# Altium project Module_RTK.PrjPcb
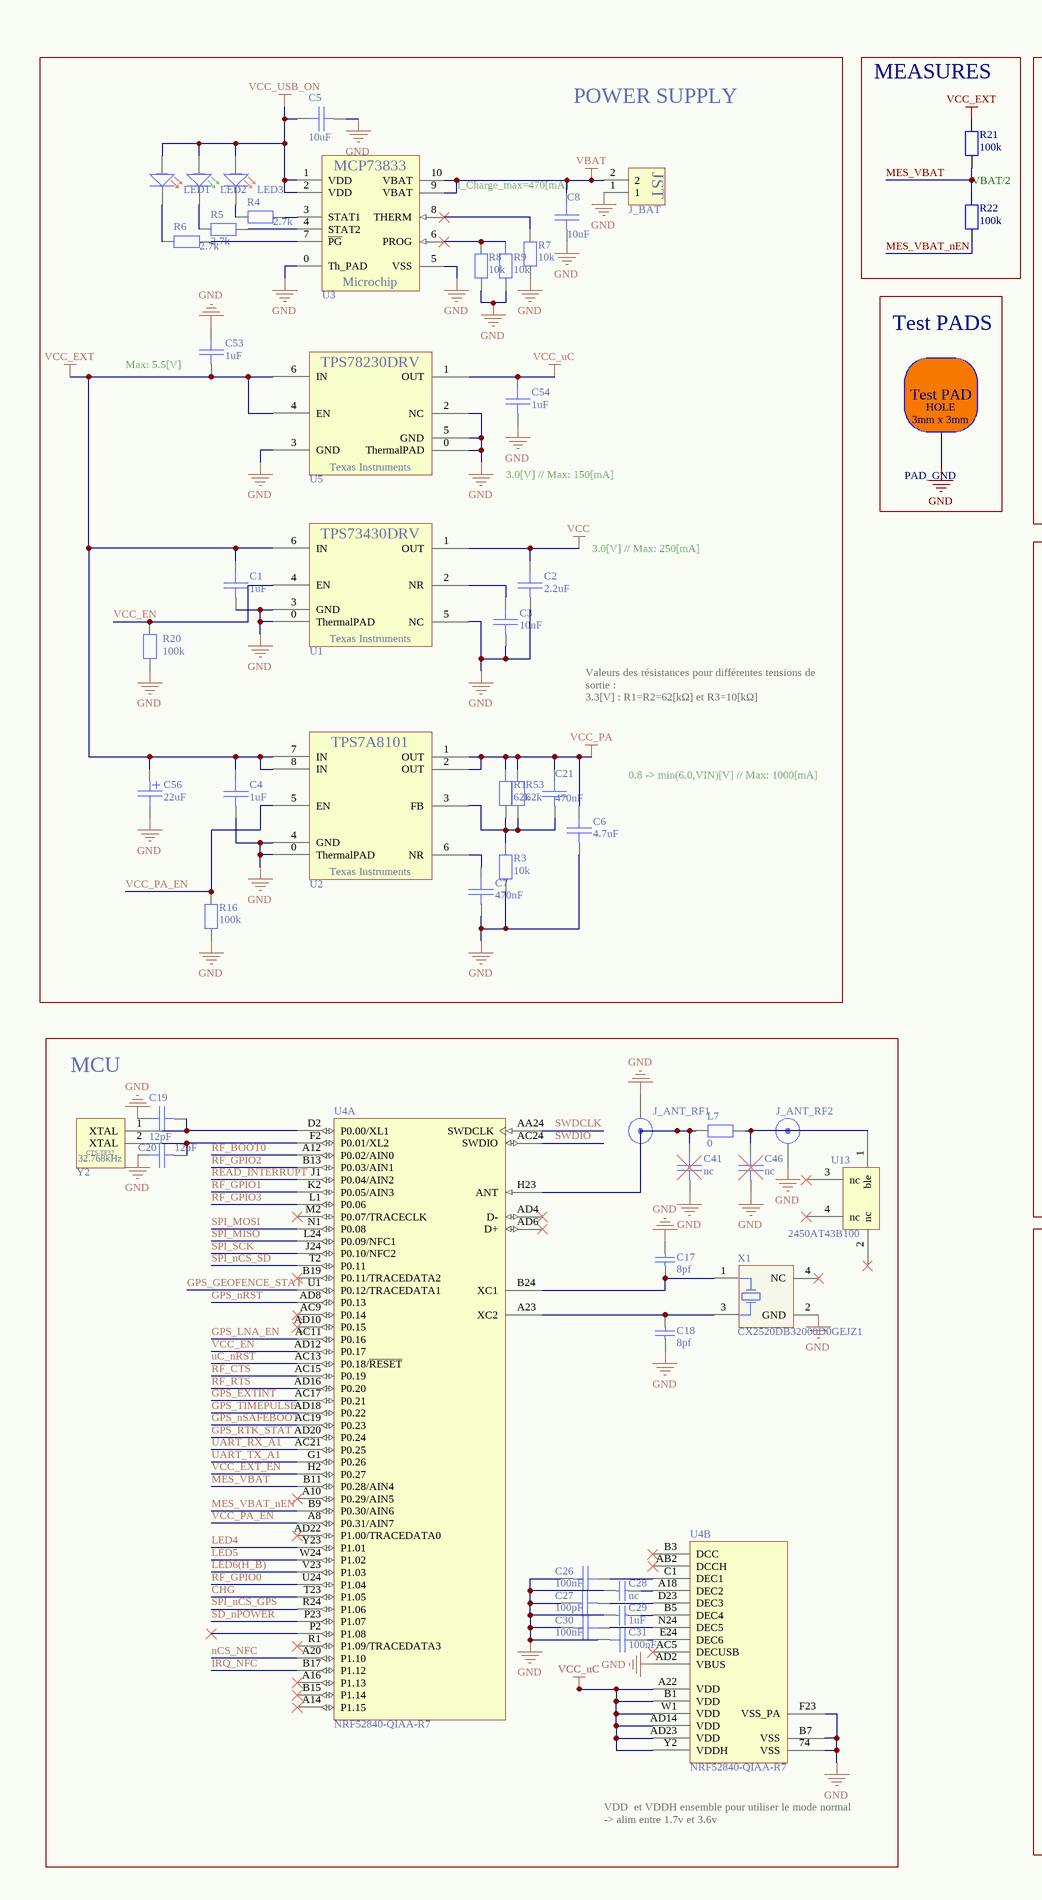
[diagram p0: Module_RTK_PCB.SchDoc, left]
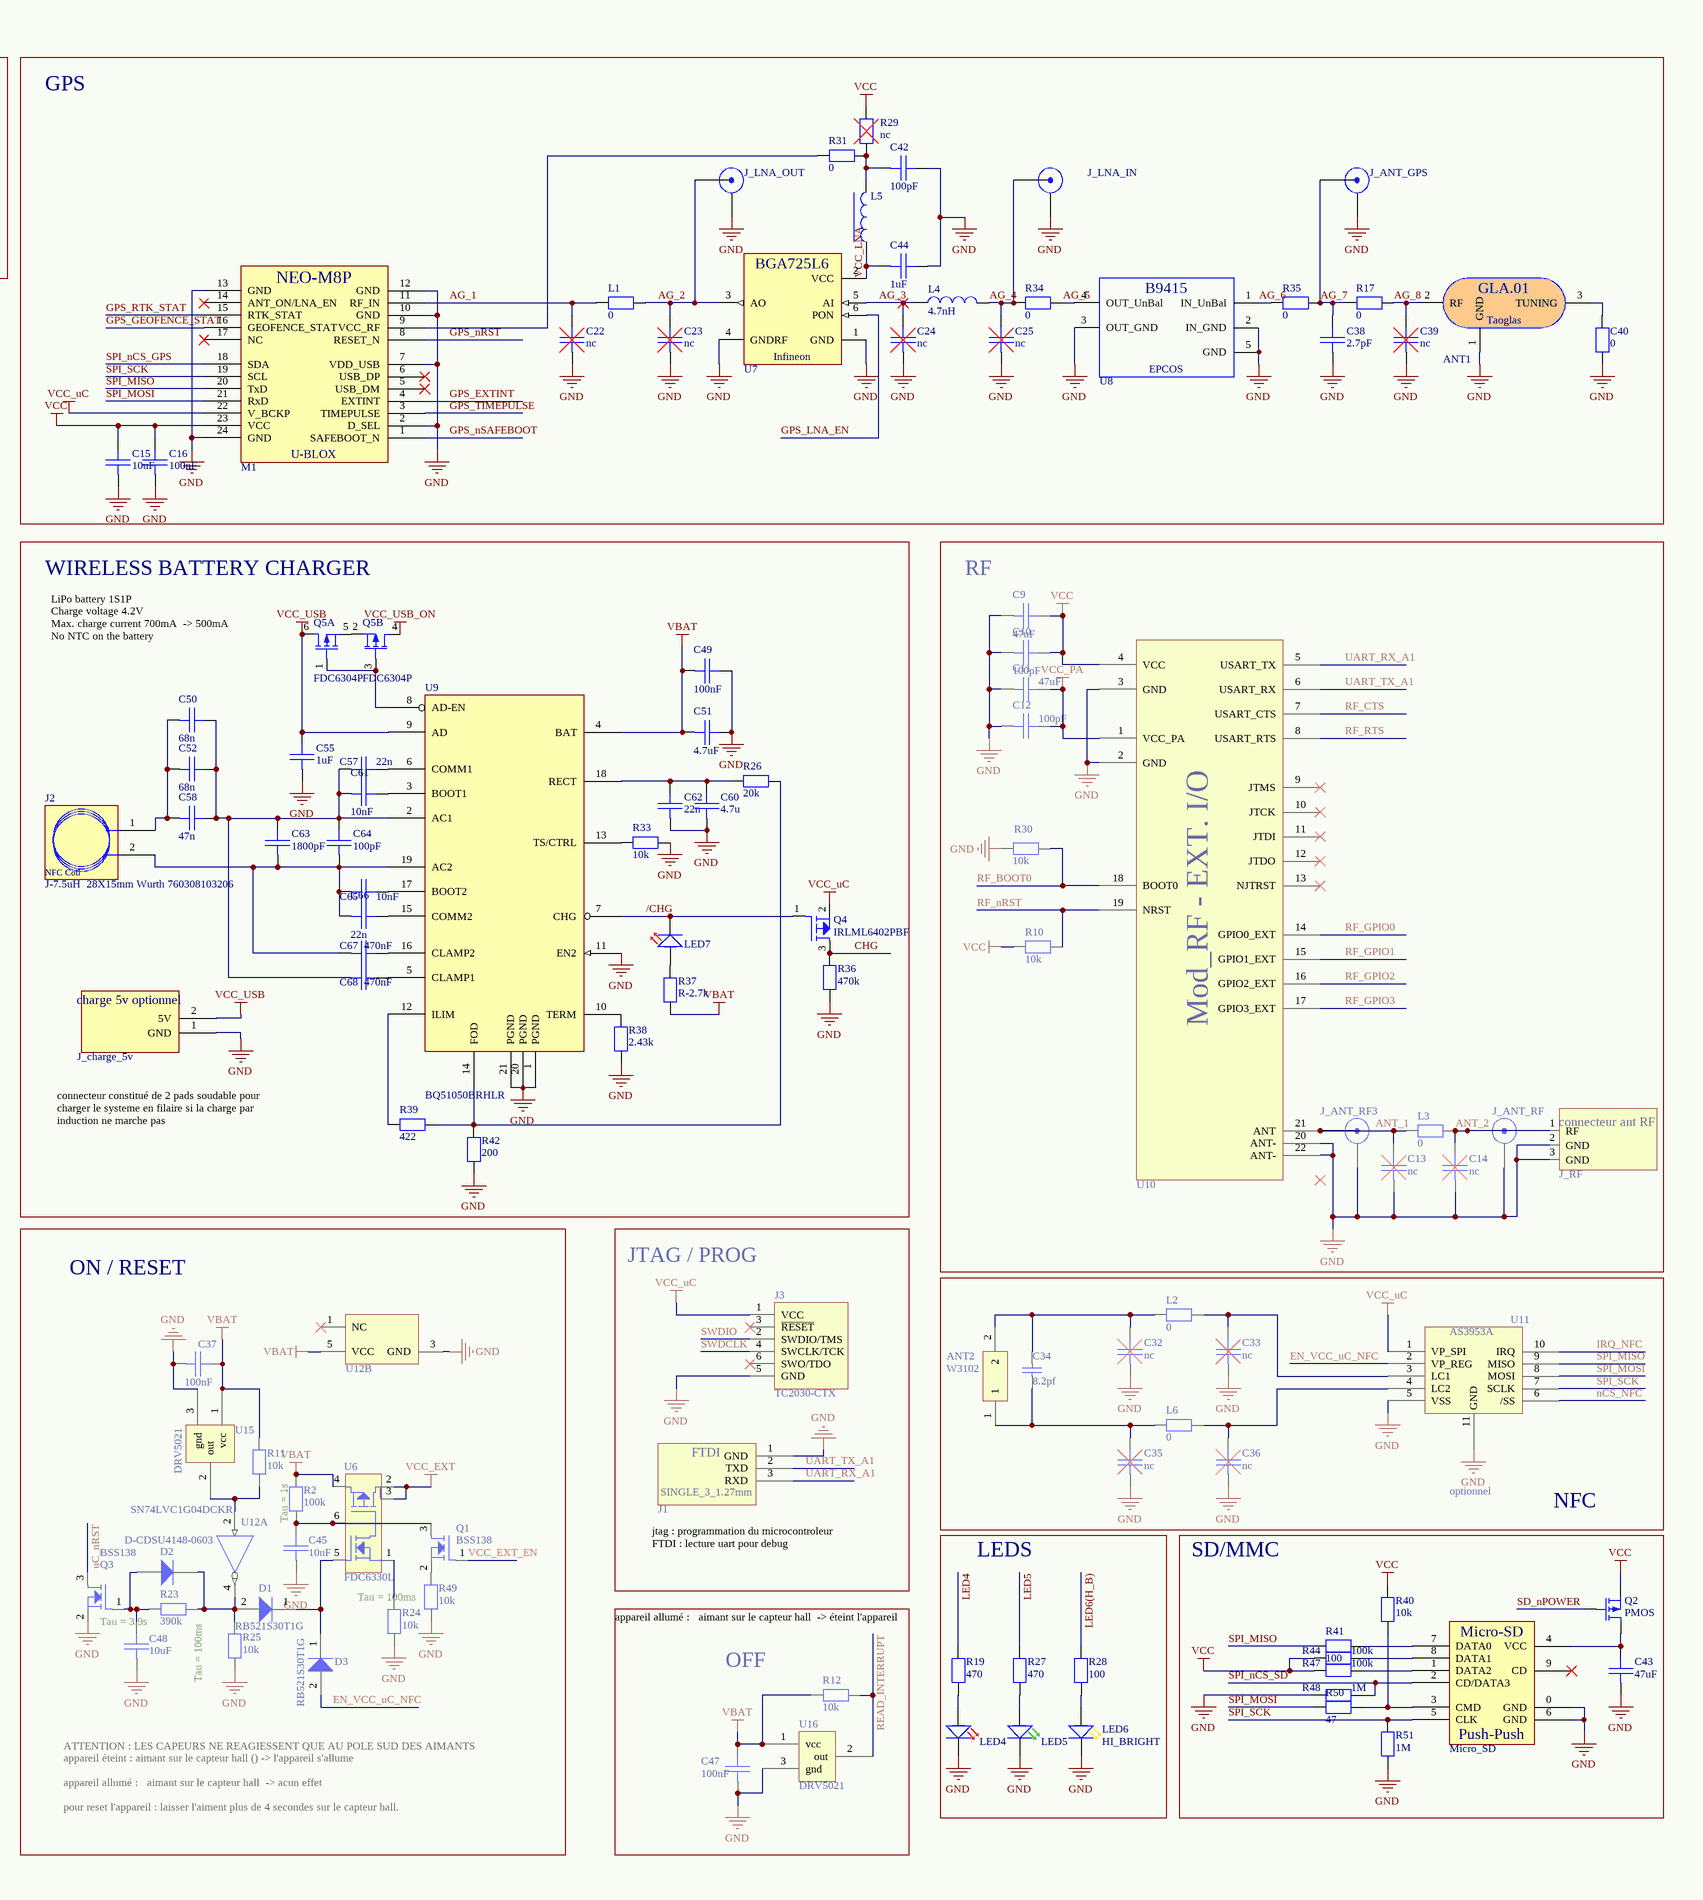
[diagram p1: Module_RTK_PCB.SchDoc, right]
1 sheet, 168 parts. Net scope: global (net labels, ports and power ports of the same name join across sheets).
Board file: Module_RTK_PCB.PcbDoc

## Sheet Module_RTK_PCB.SchDoc: Module_RTK
size A2; DrawnBy: A.B; Organization: MIS Institute; Address1: HEIG-VD; Address2: Rue Galilée 15; Address3: 1400 Yverdon-les-Bains; Address4: Switzerland; PageSetup: Record=PageOptions¦CenterHorizontal=True¦CenterVertical=True¦PrintScale=0.50¦XCorrection=1.00¦YCorrection=1.00¦PrintKind=0¦BorderSize=5000000¦LeftOffset=0¦BottomOffset=0¦Orientation=2¦PaperLength=1000¦PaperWidth=1000¦Scale=100¦PaperSource=7¦PrintQuality=-3¦MediaType=1¦DitherType=10¦PrintScaleMode=1¦PaperKind=A4 (210 x 297 mm)¦PaperIndex=9

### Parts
ANT1  Taoglas-GLA.01  [Taoglas-GLA.01]  (value not drawn)
ANT2  W3102  [W3102]
C1  value 1uF  [SM/C_0805]  (hidden comment: C-1uF-0805)
C2  value 2.2uF  [SM/C_0805]  (hidden comment: C-2.2uF-0805)
C3  value 10nF  [SM/C_0603]  (hidden comment: C-10nF-0603)
C4  value 1uF  [SM/C_0805]  (hidden comment: C-1uF-0805)
C5  value 10uF  [SM/C_0603]  (hidden comment: C-10uF-0603)
C6  value 4.7uF  [SM/C_0805]  (hidden comment: C-4.7uF-0805)
C7  value 470nF  [SM/C_0603]  (hidden comment: C-470nF-0603)
C8  value 10uF  [SM/C_0603]  (hidden comment: C-10uF-0603)
C9  value 47uF  [SM/C_0805]  (hidden comment: C-47uF-0805)
C10  value 100pF  [SM/C_0603]  (hidden comment: C-100pF-0603)
C11  value 47uF  [SM/C_0805]  (hidden comment: C-47uF-0805)
C12  value 100pF  [SM/C_0603]  (hidden comment: C-100pF-0603)
C13  value nc  [SM/C_0402]  (hidden comment: C-nc-0402)
C14  value nc  [SM/C_0402]  (hidden comment: C-nc-0402)
C15  value 10uF  [SM/C_0603]  (hidden comment: C-10uF-0603)
C16  value 100nF  [SM/C_0603]  (hidden comment: C-100nF-0603)
C17  8pf  [CAPC1608X90X35LL15T15]
C18  8pf  [CAPC1608X90X35LL15T15]
C19  value 12pF  [SM/C_0603]  (hidden comment: C-12pF-0603-2%-NP0)
C20  value 12pF  [SM/C_0603]  (hidden comment: C-12pF-0603-2%-NP0)
C21  value 470nF  [SM/C_0603]  (hidden comment: C-470nF-0603)
C22  value nc  [SM/C_0402]  (hidden comment: C-nc-0402)
C23  value nc  [SM/C_0402]  (hidden comment: C-nc-0402)
C24  value nc  [SM/C_0402]  (hidden comment: C-nc-0402)
C25  value nc  [SM/C_0402]  (hidden comment: C-nc-0402)
C26  value 100nF  [SM/C_0603]  (hidden comment: C-100nF-0603)
C27  value 100pF  [SM/C_0402]  (hidden comment: C-100pF 0402 NPO 5%)
C28  nc  [CAPC1709X95X35LL10T25]
C29  1uF  [CAPC1709X95X35LL10T25]
C30  value 100nF  [SM/C_0603]  (hidden comment: C-100nF-0603)
C31  value 100nF  [SM/C_0603]  (hidden comment: C-100nF-0603)
C32  value nc  [SM/C_0402]  (hidden comment: C-nc-0402)
C33  value nc  [SM/C_0402]  (hidden comment: C-nc-0402)
C34  value 8.2pf  [CAPC1508X91X25LL25T13]  (hidden comment: 06032U8R2CAT2A)
C35  value nc  [SM/C_0402]  (hidden comment: C-nc-0402)
C36  value nc  [SM/C_0402]  (hidden comment: C-nc-0402)
C37  value 100nF  [SM/C_0603]  (hidden comment: C-100nF-0603)
C38  value 2.7pF  [SM/C_0402]  (hidden comment: C-2.7pF-0402)
C39  value nc  [SM/C_0402]  (hidden comment: C-nc-0402)
C40  value 0  [SM/R_0402]  (hidden comment: R-0-0402)
C41  value nc  [SM/C_0402]  (hidden comment: C-nc-0402)
C42  value 100pF  [SM/C_0402]  (hidden comment: C-100pF-0402)
C43  value 47uF  [SM/C_0805]  (hidden comment: C-47uF-0805)
C44  value 1uF  [SM/C_0603]  (hidden comment: C-1uF-0603)
C45  value 10uF  [SM/C_0603]  (hidden comment: C-10uF-0603)
C46  value nc  [SM/C_0402]  (hidden comment: C-nc-0402)
C47  value 100nF  [SM/C_0603]  (hidden comment: C-100nF-0603)
C48  value 10uF  [SM/C_0603]  (hidden comment: C-10uF-0603)
C49  value 100nF  [SM/C_0603]  (hidden comment: C-100nF-0603)
C50  value 68n  [SM/C_0402]  (hidden comment: C-68n 0402 X7R)
C51  value 4.7uF  [SM/C_0603]  (hidden comment: C-4.7uF-0603)
C52  value 68n  [SM/C_0402]  (hidden comment: C-68n 0402 X7R)
C53  value 1uF  [SM/C_0603]  (hidden comment: C-1uF-0603)
C54  value 1uF  [SM/C_0603]  (hidden comment: C-1uF-0603)
C55  value 1uF  [SM/C_0805]  (hidden comment: C-1uF-0805)
C56  value 22uF  [SM/C_0805_POL]  (hidden comment: C-22uF-0805-6.3V-TANT)
C57  value 22n  [SM/C_0402]  (hidden comment: C-22n 0402 X7R)
C58  value 47n  [SM/C_0603]  (hidden comment: C-47n 0603 X7R)
C60  value 4.7u  [SM/C_0603]  (hidden comment: C-4.7u 0603 X5R 16V)
C61  value 10nF  [SM/C_0402]  (hidden comment: C-10nF 0402 X7R 5%)
C62  value 22n  [SM/C_0402]  (hidden comment: C-22n 0402 X7R 16V)
C63  value 1800pF  [SM/C_0603]  (hidden comment: C-1800pF 0603 NPO 5%)
C64  value 100pF  [SM/C_0402]  (hidden comment: C-100pF 0402 NPO 5%)
C65  value 10nF  [SM/C_0402]  (hidden comment: C-10nF 0402 X7R 5%)
C66  value 22n  [SM/C_0402]  (hidden comment: C-22n 0402 X7R)
C67  value 470nF  [SM/C_0603]  (hidden comment: C-470nF-0603)
C68  value 470nF  [SM/C_0603]  (hidden comment: C-470nF-0603)
D1  RB521S30T1G  [ONSC-SOD-523-2-502-01_V]
D2  D-CDSU4148-0603  [0603/SOD-523F_Diode]
D3  RB521S30T1G  [ONSC-SOD-523-2-502-01_V]
J1  FTDI  [SINGLE_3_1.27mm]  (value not drawn)
J2  J-7.5uH  28X15mm Wurth 760308103206  [WE-WPCC]
J3  TC2030-CTX  [TC2030-IDC]  (no BOM)
J_ANT_GPS  U.FL-R-SMT  [U.FL-R-SMT]  (value not drawn)
J_ANT_RF  U.FL-R-SMT  [U.FL-R-SMT]  (value not drawn)
J_ANT_RF1  U.FL-R-SMT  [U.FL-R-SMT]  (value not drawn)
J_ANT_RF2  U.FL-R-SMT  [U.FL-R-SMT]  (value not drawn)
J_ANT_RF3  U.FL-R-SMT  [U.FL-R-SMT]  (value not drawn)
J_BAT  S2B-PH-K-S  [S2B-PH-K-S]  (value not drawn)
J_charge_5v  charge 5v optionnel (fil a souder)  [2 pads soudable]  (value not drawn)
J_LNA_IN  U.FL-R-SMT  [U.FL-R-SMT]  (value not drawn)
J_LNA_OUT  U.FL-R-SMT  [U.FL-R-SMT]  (value not drawn)
J_RF  FTDI  [connecteur ant RF]  (value not drawn)
L1  value 0  [SM/R_0402]  (hidden comment: R-0-0402)
L2  value 0  [SM/R_0402]  (hidden comment: R-0-0402)
L3  value 0  [SM/R_0402]  (hidden comment: R-0-0402)
L4  value 4.7nH  [SM/L_0402]  (hidden comment: L-4.7nH-0402)
L5  Lfe-60R-0603-1.2A  [SM/L_0603 (1608)]  (value not drawn)
L6  value 0  [SM/R_0402]  (hidden comment: R-0-0402)
L7  value 0  [SM/R_0402]  (hidden comment: R-0-0402)
LED1  LED-RED-0603  [SM/D_0603]  (value not drawn)
LED2  LED-GREEN-0603  [SM/D_0603]  (value not drawn)
LED3  LED-ORANGE-0603  [SM/D_0603]  (value not drawn)
LED4  LED-RED-0603  [SM/D_0603]  (value not drawn)
LED5  LED-GREEN-0603  [SM/D_0603]  (value not drawn)
LED6  LED-AMBER-0603-HI_BRIGHT  [SM/D_0603]  (value not drawn)
LED7  LED-RED-0603  [SM/D_0603]  (value not drawn)
M1  NEO-M8P NEW!!  [NEO-7]  (value not drawn)
Micro_SD  Micro_SD-Push_Push  [Amphenol-10100660]  (value not drawn)
PAD_GND  Test_PAD_HOLE_3x3mm  [Test_PAD_HOLE_3x3mm]  (value not drawn)
Q1  BSS138  [SOT23_0.915]
Q2  PMOS  [SOT-323]
Q3  BSS138  [SOT23_0.915]
Q4  IRLML6402PBF  [SOT23_0.915]
Q5  FDC6304P  [supersot_6]  (parts A,B of 2)
R1  value 62k  [SM/R_0603]  (hidden comment: R-62k-0603-0.1%)
R2  value 100k  [SM/R_0603]  (hidden comment: R-100k-0603)
R3  value 10k  [SM/R_0603]  (hidden comment: R-10k-0603-0.1%)
R4  value 2.7k  [SM/R_0603]  (hidden comment: R-2.7k-0603)
R5  value 2.7k  [SM/R_0603]  (hidden comment: R-2.7k-0603)
R6  value 2.7k  [SM/R_0603]  (hidden comment: R-2.7k-0603)
R7  value 10k  [SM/R_0603]  (hidden comment: R-10k-0603-0.1%)
R8  value 10k  [SM/R_0603]  (hidden comment: R-10k-0603-0.1%)
R9  value 10k  [SM/R_0603]  (hidden comment: R-10k-0603-0.1%)
R10  value 10k  [SM/R_0603]  (hidden comment: R-10k-0603)
R11  value 10k  [SM/R_0603]  (hidden comment: R-10k-0603)
R12  value 10k  [SM/R_0603]  (hidden comment: R-10k-0603)
R16  value 100k  [SM/R_0603]  (hidden comment: R-100k-0603)
R17  value 0  [SM/R_0402]  (hidden comment: R-0-0402)
R19  value 470  [SM/R_0603]  (hidden comment: R-470-0603)
R20  value 100k  [SM/R_0603]  (hidden comment: R-100k-0603)
R21  value 100k  [SM/R_0603]  (hidden comment: R-100k-0603-0.1%)
R22  value 100k  [SM/R_0603]  (hidden comment: R-100k-0603-0.1%)
R23  value 390k  [SM/R_0603]  (hidden comment: R-390k-0603)
R24  value 10k  [SM/R_0603]  (hidden comment: R-10k-0603)
R25  value 10k  [SM/R_0603]  (hidden comment: R-10k-0603)
R26  value 20k  [SM/R_0603]  (hidden comment: R-20k-0603)
R27  value 470  [SM/R_0603]  (hidden comment: R-470-0603)
R28  value 100  [SM/R_0603]  (hidden comment: R-100-0603)
R29  value nc  [SM/R_0603]  (hidden comment: R-nc)
R30  value 10k  [SM/R_0603]  (hidden comment: R-10k-0603)
R31  value 0  [SM/R_0603]  (hidden comment: R-0-0603)
R33  value 10k  [SM/R_0603]  (hidden comment: R-10k-0603)
R34  value 0  [SM/R_0402]  (hidden comment: R-0-0402)
R35  value 0  [SM/R_0402]  (hidden comment: R-0-0402)
R36  value 470k  [SM/R_0603]  (hidden comment: R-470k-0603)
R37  value R-2.7k  [SM/R_0603]  (hidden comment: R-2.7k-0603)
R38  value 2.43k  [SM/R_0603]  (hidden comment: R-2.43k-0603)
R39  value 422  [SM/R_0603]  (hidden comment: R-422-0603)
R40  value 10k  [SM/R_0603]  (hidden comment: R-10k-0603)
R41  value 100  [SM/R_0603]  (hidden comment: R-100-0603)
R42  value 200  [SM/R_0603]  (hidden comment: R-200-0603)
R44  value 100k  [SM/R_0603]  (hidden comment: R-100k-0603)
R47  value 100k  [SM/R_0603]  (hidden comment: R-100k-0603)
R48  value 1M  [SM/R_0603]  (hidden comment: R-1M-0603)
R49  value 10k  [SM/R_0603]  (hidden comment: R-10k-0603)
R50  value 47  [SM/R_0603]  (hidden comment: R-47-0603)
R51  value 1M  [SM/R_0603]  (hidden comment: R-1M-0603)
R53  value 62k  [SM/R_0603]  (hidden comment: R-62k-0603-0.1%)
U1  TPS73430DRV  [SON-6_DRV]  (value not drawn)
U2  TPS7A8101  [SON-8_DRB]  (value not drawn)
U3  MCP73833  [DFN-MF10]  (value not drawn)
U4  NRF52840-QIAA-R7  [NRSC-AQFN-73]  (parts A,B of 2)
U5  TPS78230DRV  [SON-6_DRV]  (value not drawn)
U6  FDC6330L  [SOT-363_0.95]
U7  BGA725L6  [INF-TSLP-6-2_V]  (value not drawn)
U8  B9415  [B9415]  (value not drawn)
U9  BQ51050BRHLR  [RHL20-3050X2050TP]
U10  Module_RF_EXT_IO_4_2  [Module_RF4_2]  (value not drawn)
U11  AS3953A  [MLPD_3x3mm_10_pin_AS3953A]  (value not drawn)
U12  SN74LVC1G04DCKR  [DCK0005A_N]  (parts A,B of 2)
U13  2450AT43B100  [2450AT43B100]
U15  DRV5021  [SOT23]
U16  DRV5021  [SOT23]
X1  CX2520DB32000D0GEJZ1  [AVX-CX2520DB32000D0GEJZ1-4_V]
Y2  32.768kHz - 20ppm - CTS-TF32  [CTS-TF32]  (value not drawn)

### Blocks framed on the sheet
POWER SUPPLY: C1-C8 C21 C53 C54 C56 J_BAT LED1-LED3 R1 R3-R9 R16 R20 R53 U1-U3 U5
MEASURES: R21 R22
GPS: ANT1 C15 C16 C22-C25 C38-C40 C42 C44 J_ANT_GPS J_LNA_IN J_LNA_OUT L1 L4 L5 M1 R17 R29 R31 R34 R35 U7 U8
Test PADS: PAD_GND
WIRELESS BATTERY CHARGER: C49-C52 C55 C57 C58 C60-C68 J2 J_charge_5v LED7 Q4 Q5 R26 R33 R36-R39 R42 U9
RF: C9-C14 J_ANT_RF J_ANT_RF3 J_RF L3 R10 R30 U10
MCU: C17-C20 C26-C31 C41 C46 J_ANT_RF1 J_ANT_RF2 L7 U4 U13 X1 Y2
ON / RESET: C37 C45 C48 D1-D3 Q1 Q3 R2 R11 R23-R25 R49 U6 U12 U15
JTAG / PROG: J1 J3
NFC: ANT2 C32-C36 L2 L6 U11
LEDS: LED4-LED6 R19 R27 R28
SD/MMC: C43 Micro_SD Q2 R40 R41 R44 R47 R48 R50 R51
OFF: C47 R12 U16

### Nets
GND: ANT1.1(GND) C1.1 C2.1 C3.1 C4.1 C5.1 C6.1 C7.1 C8.1 C9.1 C10.1 C11.1 C12.1 C13.1 C14.1 C15.1 C16.1 C17.2 C18.1 C19.2 C20.2 C22.1 C23.1 C24.1 C25.1 C26.1 C27.2 C28.1 C29.1 C30.1 C31.1 C32.1 C33.1 C35.1 C36.1 C37.1 C38.1 C39.1 C40.1 C41.1 C42.2 C43.1 C44.2 C45.1 C46.1 C47.1 C48.1 C49.2 C51.2 C53.2 C54.1 C55.1 C56.2 C60.1 C62.1 J1.1(GND) J3.5(GND) J_ANT_GPS.2(Y) J_ANT_RF.2(Y) J_ANT_RF1.2(Y) J_ANT_RF2.2(Y) J_ANT_RF3.2(Y) J_BAT.1 J_charge_5v.1(GND) J_LNA_IN.2(Y) J_LNA_OUT.2(Y) J_RF.2(GND) J_RF.3(GND) LED4.2(K) LED5.2(K) LED6.2(K) M1.2(D_SEL) M1.7(VDD_USB) M1.10(GND) M1.12(GND) M1.13(GND) M1.24(GND) Micro_SD.0(GND) Micro_SD.6(GND) PAD_GND.0 Q3.2(S) R3.1 R7.1 R8.1 R9.1 R16.1 R20.1 R24.1 R25.2 R30.1 R33.2 R36.1 R38.1 R42.1 R48.2 R49.2 R51.1 U1.0(ThermalPAD) U1.3(GND) U1.5(NC) U2.0(ThermalPAD) U2.4(GND) U3.0(Th_PAD) U3.5(VSS) U4.74(VSS) U4.AD2(VBUS) U4.B7(VSS) U4.F23(VSS_PA) U5.0(ThermalPAD) U5.2(NC) U5.3(GND) U5.5(GND) U7.1(GND) U7.4(GNDRF) U8.2(IN_GND) U8.3(OUT_GND) U8.5(GND) U9.1(PGND) U9.11(EN2) U9.20(PGND) U9.21(PGND) U10.2(GND) U10.3(GND) U10.20(ANT-) U10.22(ANT-) U11.5(VSS) U11.11(GND) U12.3(GND) U15.3(gnd) U16.3(gnd) X1.2(GND)
VBAT: C8.2 C37.2 C47.2 C49.1 C51.1 J_BAT.2 R2.2 R11.1 R12.1 R37.2 U3.9(VBAT) U3.10(VBAT) U6.4(Vin) U9.4(BAT) U12.5(VCC) U15.1(vcc) U16.1(vcc)
VCC: C2.2 C9.2 C10.2 C15.2 C16.2 M1.23(VCC) Q2.2(S) R10.2 R29.2 R40.2 R44.1 R47.1 U1.1(OUT) U10.4(VCC)
VCC_EXT: C1.2 C4.2 C53.1 C56.1 R21.2 U1.6(IN) U2.7(IN) U2.8(IN) U5.4(EN) U5.6(IN) U6.2(D1Vout) U6.3(Vout)
VCC_PA: C6.2 C11.2 C12.2 C21.2 R1.2 R53.2 U2.1(OUT) U2.2(OUT) U10.1(VCC_PA)
VCC_uC: C54.2 J3.1(VCC) M1.22(V_BCKP) Q4.2(S) U4.A22(VDD) U4.AD14(VDD) U4.AD23(VDD) U4.B1(VDD) U4.W1(VDD) U4.Y2(VDDH) U5.1(OUT) U11.1(VP_SPI)
VCC_USB: C55.2 J_charge_5v.2(5V) Q5.6(D1) U9.9(AD)
VCC_USB_ON: C5.2 LED1.1(A) LED2.1(A) LED3.1(A) Q5.4(D2) U3.1(VDD) U3.2(VDD)
/CHG: LED7.2(K) Q4.1(G) U9.7(CHG)
AG_1: C22.2 L1.1 M1.11(RF_IN)
AG_2: C23.2 J_LNA_OUT.1(X) L1.2 U7.3(AO)
AG_3: C24.2 L4.1 U7.5(AI)
AG_4: C25.2 J_LNA_IN.1(X) L4.2 R34.1
AG_5: R34.2 U8.4(OUT_UnBal)
AG_6: R35.1 U8.1(IN_UnBal)
AG_7: C38.2 J_ANT_GPS.1(X) R17.1 R35.2
AG_8: ANT1.2(RF) C39.2 R17.2
ANT_1: C13.2 J_ANT_RF3.1(X) L3.1 U10.21(ANT)
ANT_2: C14.2 J_ANT_RF.1(X) J_RF.1(RF) L3.2
CHG: Q4.3(D) R36.2 U4.T23(P1.05)
EN_VCC_uC_NFC: D3.2(A) U11.2(VP_REG)
GPS_EXTINT: M1.4(EXTINT) U4.AC17(P0.21)
GPS_GEOFENCE_STAT: M1.16(GEOFENCE_STAT) U4.U1(P0.12/TRACEDATA1)
GPS_LNA_EN: U4.AC11(P0.16) U7.6(PON)
GPS_nRST: M1.8(RESET_N) U4.AD8(P0.13)
GPS_nSAFEBOOT: M1.1(SAFEBOOT_N) U4.AC19(P0.23)
GPS_RTK_STAT: M1.15(RTK_STAT) U4.AD20(P0.24)
GPS_TIMEPULSE: M1.3(TIMEPULSE) U4.AD18(P0.22)
IRQ_NFC: U4.B17(P1.12) U11.10(IRQ)
LED4: R19.2 U4.Y23(P1.01)
LED5: R27.2 U4.W24(P1.02)
LED6(H_B): R28.2 U4.V23(P1.03)
MES_VBAT: R21.1 R22.2 U4.B11(P0.28/AIN4)
MES_VBAT_nEN: R22.1 U4.B9(P0.30/AIN6)
nCS_NFC: U4.A20(P1.10) U11.6(/SS)
READ_INTERRUPT: R12.2 U4.J1(P0.04/AIN2) U16.2(out)
RF_BOOT0: R30.2 U4.A12(P0.02/AIN0) U10.18(BOOT0)
RF_CTS: U4.AC15(P0.19) U10.7(USART_CTS)
RF_GPIO0: U4.U24(P1.04) U10.14(GPIO0_EXT)
RF_GPIO1: U4.K2(P0.05/AIN3) U10.15(GPIO1_EXT)
RF_GPIO2: U4.B13(P0.03/AIN1) U10.16(GPIO2_EXT)
RF_GPIO3: U4.L1(P0.06) U10.17(GPIO3_EXT)
RF_nRST: R10.1 U10.19(NRST)
RF_RTS: U4.AD16(P0.20) U10.8(USART_RTS)
SD_nPOWER: Q2.1(G) U4.P23(P1.07)
SPI_MISO: M1.20(TxD) R41.1 U4.L24(P0.09/NFC1) U11.9(MISO)
SPI_MOSI: M1.21(RxD) R50.1 U4.N1(P0.08) U11.8(MOSI)
SPI_nCS_GPS: M1.18(SDA) U4.R24(P1.06)
SPI_nCS_SD: Micro_SD.2(CD/DATA3) R48.1 U4.T2(P0.11)
SPI_SCK: M1.19(SCL) Micro_SD.5(CLK) R51.2 U4.J24(P0.10/NFC2) U11.7(SCLK)
SWDCLK: J3.4(SWCLK/TCK) U4.AA24(SWDCLK)
SWDIO: J3.2(SWDIO/TMS) U4.AC24(SWDIO)
UART_RX_A1: J1.3(RXD) U4.AC21(P0.25) U10.5(USART_TX)
UART_TX_A1: J1.2(TXD) U4.G1(P0.26) U10.6(USART_RX)
uC_nRST: Q3.3(D) U4.AC13(P0.18/~{RESET})
VCC_EN: R20.2 U1.4(EN) U4.AD12(P0.17)
VCC_EXT_EN: Q1.1(G) U4.H2(P0.27)
VCC_LNA: C44.1 L5.1 U7.2(VCC)
VCC_PA_EN: R16.2 U2.5(EN) U4.A8(P0.31/AIN7)
NetANT1_3: ANT1.3(TUNING) C40.2
NetANT2_1: ANT2.1 C34.1 C35.2 L6.1
NetANT2_2: ANT2.2 C32.2 C34.2 L2.1
NetC3_2: C3.2 U1.2(NR)
NetC7_2: C7.2 U2.6(NR)
NetC17_1: C17.1 U4.B24(XC1) X1.1(HOT)
NetC18_2: C18.2 U4.A23(XC2) X1.3(HOT)
NetC19_1: C19.1 U4.D2(P0.00/XL1) Y2.1(XTAL)
NetC20_1: C20.1 U4.F2(P0.01/XL2) Y2.2(XTAL)
NetC21_1: C21.1 R1.1 R3.2 R53.1 U2.3(FB)
NetC26_2: C26.2 U4.C1(DEC1)
NetC27_1: C27.1 U4.D23(DEC3)
NetC28_2: C28.2 U4.A18(DEC2)
NetC29_2: C29.2 U4.B5(DEC4)
NetC30_2: C30.2 U4.N24(DEC5)
NetC31_2: C31.2 U4.E24(DEC6)
NetC33_2: C33.2 L2.2 U11.3(LC1)
NetC36_2: C36.2 L6.2 U11.4(LC2)
NetC41_2: C41.2 J_ANT_RF1.1(X) L7.1 U4.H23(ANT)
NetC42_1: C42.1 L5.2 R29.1 R31.2
NetC43_2: C43.2 Micro_SD.4(VCC) Q2.3(D)
NetC45_2: C45.2 Q1.3(D) R2.1 U6.6(R1C1)
NetC46_2: C46.2 J_ANT_RF2.1(X) L7.2 U13.1(ble)
NetC48_2: C48.2 D2.1(A) Q3.1(G) R23.1
NetC50_1: C50.1 C52.1 C58.1 J2.1
NetC50_2: C50.2 C52.2 C57.1 C58.2 C61.1 C63.2 C64.2 C68.1 U9.2(AC1)
NetC57_2: C57.2 U9.6(COMM1)
NetC60_2: C60.2 C62.2 R26.1 U9.18(RECT)
NetC61_2: C61.2 U9.3(BOOT1)
NetC63_1: C63.1 C64.1 C65.1 C66.1 C67.1 J2.2 U9.19(AC2)
NetC65_2: C65.2 U9.17(BOOT2)
NetC66_2: C66.2 U9.15(COMM2)
NetC67_2: C67.2 U9.16(CLAMP2)
NetC68_2: C68.2 U9.5(CLAMP1)
NetD1_1: D1.1(K) D3.1(K) U6.5(ON/OFF)
NetD1_2: D1.2(A) D2.2(K) R23.2 R25.1 U12.4(Y)
NetLED1_2: LED1.2(K) R6.1
NetLED2_2: LED2.2(K) R5.1
NetLED3_2: LED3.2(K) R4.1
NetLED4_1: LED4.1(A) R19.1
NetLED5_1: LED5.1(A) R27.1
NetLED6_1: LED6.1(A) R28.1
NetLED7_1: LED7.1(A) R37.1
NetM1_9: M1.9(VCC_RF) R31.1
NetMicro_SD_1: Micro_SD.1(DATA2) R47.2
NetMicro_SD_3: Micro_SD.3(CMD) R40.1 R50.2
NetMicro_SD_7: Micro_SD.7(DATA0) R41.2
NetMicro_SD_8: Micro_SD.8(DATA1) R44.2
NetQ1_2: Q1.2(S) R49.1
NetQ5_1: Q5.1(G1) Q5.3(G2) U9.8(AD-EN)
NetQ5_2: Q5.2(S2) Q5.5(S1)
NetR4_2: R4.2 U3.3(STAT1)
NetR5_2: R5.2 U3.4(STAT2)
NetR6_2: R6.2 U3.7(~{PG})
NetR7_2: R7.2 U3.8(THERM)
NetR8_2: R8.2 R9.2 U3.6(PROG)
NetR11_2: R11.2 U12.2(A) U15.2(out)
NetR24_2: R24.2 U6.1(R2)
NetR26_2: R26.2 R39.2 R42.2 U9.14(FOD)
NetR33_1: R33.1 U9.13(TS/CTRL)
NetR38_2: R38.2 U9.10(TERM)
NetR39_1: R39.1 U9.12(ILIM)

Not connected (* = marked no-connect by the designer): J3 3(~{RESET})* 6(SWO/TDO)*; M1 5(USB_DM)* 6(USB_DP)* 14(ANT_ON/LNA_EN)* 17(NC)*; Micro_SD 9(CD)*; U4 A10(P0.29/AIN5)* A14(P1.15)* A16(P1.13)* AB2(DCCH)* AC5(DECUSB)* AC9(P0.14)* AD4(D-)* AD6(D+)* AD10(P0.15)* AD22(P1.00/TRACEDATA0)* B3(DCC)* B15(P1.14)* B19(P0.11/TRACEDATA2)* M2(P0.07/TRACECLK)* P2(P1.08)* R1(P1.09/TRACEDATA3)*; U10 9(JTMS)* 10(JTCK)* 11(JTDI)* 12(JTDO)* 13(NJTRST)*; U12 1(NC)*; U13 2(nc)* 3(nc)* 4(nc)*; X1 4(NC)*

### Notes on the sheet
- VBAT/2
- (near C8) I_Charge_max=470[mA]
- (near C53) Max: 5.5[V]
- 3.0[V] // Max: 150[mA]
- 3.0[V] // Max: 250[mA]
- Valeurs des résistances pour différentes tensions de sortie :
  3.3[V] : R1=R2=62[kΩ] et R3=10[kΩ]
- LiPo battery 1S1P
  Charge voltage 4.2V
  Max. charge current 700mA  -> 500mA
  No NTC on the battery
- 0.8 -> min(6.0,VIN)[V] // Max: 1000[mA]
- connecteur constitué de 2 pads soudable pour charger le systeme en filaire si la charge par induction ne marche pas
- (near R2) Tau = 1s
- optionnel
- Tau = 100ms
- (near J1) jtag : programmation du microcontroleur   FTDI : lecture uart pour debug
- Tau = 3.9s
- appareil allumé :   aimant sur le capteur hall  -> éteint l'appareil
- (near R23) Tau = 100ms
- VDD  et VDDH ensemble pour utiliser le mode normal
  -> alim entre 1.7v et 3.6v
- ATTENTION : LES CAPEURS NE REAGIESSENT QUE AU POLE SUD DES AIMANTS                                                                                                                                               appareil éteint : aimant sur le capteur hall () -> l'appareil s'allume
  appareil allumé :   aimant sur le capteur hall  -> acun effet
  pour reset l'appareil : laisser l'aiment plus de 4 secondes sur le capteur hall.

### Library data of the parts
ANT1 = Taoglas-GLA.01: GPS Loop Antenna
ANT2 = W3102: Antenna; Manufacturer_Name: PulseLarsen Antennas
C1 C4 C55 = C-1uF-0805: Voltage: 16V; Fabricant_Ref: GRM188R71E104JA01D; Fabricant: Murata; Tolerance: 10%; Technologie: X7R
C2 = C-2.2uF-0805: Voltage: 16V; Fabricant_Ref: C2012X7R1C225K125AB; Fabricant: Murata; Tolerance: 10%; Technologie: X7R
C3 = C-10nF-0603: Voltage: 50V; Fabricant_Ref: GRM188R71H103KA01D; Fabricant: Murata; Tolerance: 10%; Technologie: X7R
C5 C8 C15 C45 C48 = C-10uF-0603: Voltage: 6.3V; Fabricant_Ref: C1608X5R0J106M080AB; Fabricant: TDK; Tolerance: 20%; Technologie: X5R
C6 = C-4.7uF-0805: Voltage: 10V; Fabricant_Ref: C2012X7R1A475K085AC; Fabricant: Murata; Tolerance: 10%; Technologie: X7R
C7 C21 C67 C68 = C-470nF-0603: Fabricant: Samsung; Fabricant_Ref: CL10B104JA8NNNC; Technologie: X7R; Tolerance: 5%; Voltage: 25V
C9 C11 C43 = C-47uF-0805: Voltage: 6.3V; Fabricant_Ref: C2012X5R0J476M125AC; Fabricant: TDK; Tolerance: 20%; Technologie: X5R
C10 C12 = C-100pF-0603: Voltage: 100V; Fabricant_Ref: GRM1885C2A101JA01D; Fabricant: Murata; Tolerance: 5%; Technologie: NPO
C13 C14 C22-C25 C32 C33 C35 C36 C39 C41 C46 = C-nc-0402: Technologie: NPO
C16 = C-100nF-0603: Voltage: 25V; Fabricant_Ref: GRM188R71E104JA01D; Fabricant: Murata; Technologie: 5%
C17 C18 = CMP-2006-04063-1: Manufacturer: AVX Interconnect / Elco; Part Number: 06031A8R0CAT2A
C19 C20 = C-12pF-0603-2%-NP0: Fabricant: Murata; Fabricant_Ref: GRM1885C1H220JA01D; Technologie: NPO; Tolerance: 5%; Voltage: 50V
C26 C30 C31 C37 C47 C49 = C-100nF-0603: Voltage: 25V; Fabricant_Ref: C1608X7R1E104K080AA; Fabricant: TDK; Tolerance: 10%; Technologie: X7R
C27 C64 = C-100pF 0402 NPO 5%: Voltage: 50V; Fabricant_Ref: 500R07N101JV4T; Fabricant: Johanson Dielectrics
C28 = CMP-2000-07531-1: Chip Capacitor, 1 uF, +/- 10%, 50 V, -55 to 125 degC, 0603 (1608 Metric), RoHS, Tape and Reel; Manufacturer: Taiyo Yuden; Capacitance: 1uF; Voltage Rating: 50V; Dielectric: X7R
C29 = CMP-2000-07531-1: Chip Capacitor, 1 uF, +/- 10%, 50 V, -55 to 125 degC, 0603 (1608 Metric), RoHS, Tape and Reel; Manufacturer: Taiyo Yuden; Voltage Rating: 50V; Dielectric: X7R
C34 = CMP-2006-04681-1: Manufacturer: AVX Interconnect / Elco
C38 = C-2.7pF-0402: Voltage: 50V; Fabricant_Ref: GRM1555C1H2R7BA01D; Fabricant: Murata; Tolerance: 0.1pF; Technologie: NPO
C40 L1-L3 L6 L7 R17 R34 R35 = R-0-0402: Fabricant_Ref: ERJ-2GE0R00X; Fabricant: Panasonic; Puissance: 100 mW; Tolerance: 1%; Tension: 50V
C42 = C-100pF-0402: Voltage: 50V; Fabricant_Ref: GRM1555C1H101FA01J; Fabricant: Murata; Tolerance: 1%; Technologie: NPO
C44 = C-1uF-0603: Voltage: 16V; Fabricant_Ref: C1608X7R1C105K080AC; Fabricant: Murata; Tolerance: 10%; Technologie: X7R
C50 C52 = C-68n 0402 X7R: Voltage: 50V; Fabricant_Ref: C1005X7R1H683K050BB; Fabricant: TDK; Tolerance: 10%
C51 = C-4.7uF-0603: Voltage: 6.3V; Fabricant_Ref: GRM188R60J475KE19D; Fabricant: Murata; Tolerance: 10%; Technologie: X5R
C53 C54 = C-1uF-0603: Voltage: 25V; Fabricant_Ref: GRM188R71E104JA01D; Fabricant: Murata; Technologie: 5%
C56 = C-22uF-0805-6.3V-TANT: Voltage: 6.3V; Fabricant_Ref: TLJP107M006R5400; Fabricant: AVX; Tolerance: 20%; Technologie: Tantale
C57 C66 = C-22n 0402 X7R: Voltage: 50V; Fabricant_Ref: GRM155R71H223KA12D; Fabricant: Murata; Tolerance: 10%
C58 = C-47n 0603 X7R: Voltage: 50V; Fabricant_Ref: GRM188R71H473KA61D; Fabricant: Murata; Tolerance: 10%
C60 = C-4.7u 0603 X5R 16V: Fabricant_Ref: GRM188R61C475KAAJD; Fabricant: Murata; Tolerance: 10%
C61 C65 = C-10nF 0402 X7R 5%: Voltage: 50V; Fabricant_Ref: C0402C103J5RACTU; Fabricant: KEMET
C62 = C-22n 0402 X7R 16V: Fabricant_Ref: 0402YC223KAT2A; Fabricant: AVX; Tolerance: 10%
C63 = C-1800pF 0603 NPO 5%: Voltage: 50V; Fabricant_Ref: GRM1885C1H182JA01D; Fabricant: Murata
D1 D3 = ONSC-D-K1A2-2: Schottky Barrier Diode, 2-Pin SOD-523, Pb-Free, Tape and Reel; Manufacturer: On Semiconductor; Configuration: Single; IFSM Max (A): 1
D2 = D-4148-0603: Fabricant: Comchip Technology; Fabricant_Ref: CSDU4148
J1 = FTDI 3 pin
J2 = WPCC_COIL: Fabricant: Würth
J3 = TC2030-CTX: ARM Cortex 10-pin Cable with 6-Pin TC2030 Plug-of-Nails Connector; Manufacturer: Tag-Connect
J_BAT = S2B-PH-K-S: JST, Through-Hole, Side entry type
J_charge_5v = charge 5v optionnel: connecteur de charge 5v si jamais il y avais des problemes avec la charge par induction. (fils a souder directement sur le pcb, pas de connecteur externe)
J_RF = conn_ant_RF
L4 = L-4.7nH-0402: I_DC: 300mA; Tolerance: 0.3nH; Fabricant: Murata; Fabricant_Ref: LQG15HN3N3S02D
L5 = Lfe-60R-0603-1.2A: ¦Z¦>200[Ω]@1.5[GHz]; I_DC: 1300mA; Tolerance: 20%; Fabricant: TDK; Fabricant_Ref: MLP2012HR47MT0S1; Value: Beads
M1 = NEO-M8P: NEW !! GNSS module for GPS/QZSS, GLONASS
Micro_SD = Micro_SD-Push_Push: Fabricant: ALPS; Fabricant_Ref: SCHD3A0100
Q1 Q3 = BSS138: MOSFET N-CH 50V 200MA SOT23-3; Manufacturer: Diodes Inc; RefMfg: BSS138-7-F
Q2 = PMOS-DMP2160UW-1.5A: Low RDS(ON)
Q4 = IRLML6402: MOSFET P-CH 20V 3.7A SOT-23; Manufacturer: International Rectifier; RefMfg: IRLML6402TRPBF
Q5 = FDC6304P: Fabricant: Fairschild
R1 R53 = R-62k-0603-0.1%: Fabricant_Ref: ERA-3AEB623V; Fabricant: Panasonic; Puissance: 100 mW; Tolerance: 0.1%; Tension: 75V
R2 R16 R20 R44 R47 = R-100k-0603: Fabricant_Ref: ERJ-3EKF1003V; Fabricant: Panasonic; Puissance: 100 mW; Tolerance: 1%; Tension: 75V
R3 R7-R9 = R-10k-0603-0.1%: Fabricant_Ref: ERA-3AEB103V; Fabricant: Panasonic; Puissance: 100 mW; Tolerance: 0.1%; Tension: 75V
R4-R6 = R-2.7k-0603: Fabricant: Panasonic; Puissance: 100 mW; Tolerance: 1%; Tension: 75V
R10-R12 R24 R25 R30 R33 R40 R49 = R-10k-0603: Fabricant_Ref: ERJ-3EKF1002V; Fabricant: Panasonic; Puissance: 100 mW; Tolerance: 1%; Tension: 75V
R19 R27 = R-470-0603: Fabricant: Panasonic; Fabricant_Ref: ERJ-3EKF4700V; Tolerance: 1%
R21 R22 = R-100k-0603-0.1%: Fabricant_Ref: ERA-3AEB104V; Fabricant: Panasonic; Puissance: 100 mW; Tolerance: 0.1%; Tension: 75V
R23 = R-390k-0603: Fabricant_Ref: ERJ-3EKF3903V; Fabricant: Panasonic; Puissance: 100 mW; Tolerance: 1%; Tension: 75V
R26 = R-20k-0603: Fabricant: Panasonic; Puissance: 100 mW; Tolerance: 1%; Tension: 75V
R28 R41 = R-100-0603: Fabricant_Ref: ERJ-3EKF1000V; Fabricant: Panasonic; Puissance: 100 mW; Tolerance: 1%; Tension: 75V
R29 = R-nc-0603
R31 = R-0-0603: Fabricant_Ref: ERJ-3GEY0R00V; Fabricant: Panasonic; Puissance: 100 mW; Tolerance: 1%; Tension: 50V
R36 = R-470k-0603: Fabricant_Ref: ERJ-3EKF4703V; Fabricant: Panasonic; Puissance: 100 mW; Tolerance: 1%; Tension: 75V
R37 = R-2.7k-0603: Fabricant_Ref: ERJ-3EKF1501V; Fabricant: Panasonic; Puissance: 100 mW; Tolerance: 1%; Tension: 75V
R38 = R-2.43k-0603: Fabricant_Ref: ERJ-3EKF2431V; Fabricant: Panasonic; Puissance: 100 mW; Tolerance: 1%; Tension: 75V
R39 = R-422-0603: Fabricant_Ref: ERJ-3EKF4220V; Fabricant: Panasonic; Puissance: 100 mW; Tolerance: 1%; Tension: 75V
R42 = R-200-0603: Fabricant_Ref: ERJ-3EKF2000V; Fabricant: Panasonic; Puissance: 100 mW; Tolerance: 1%; Tension: 75V
R48 R51 = R-1M-0603: Fabricant_Ref: ERJ-3EKF1004V; Fabricant: Panasonic; Puissance: 100 mW; Tolerance: 1%; Tension: 75V
R50 = R-47-0603: Fabricant_Ref: ERJ-3EKF47R0V; Fabricant: Panasonic; Puissance: 100 mW; Tolerance: 1%; Tension: 75V
U3 = MCP73833: Stand-Alone Linear Li-Ion/Li-Polymer Charge Management Controller with Power-Good Output, 4.2V, 10-Pin DFN, Industrial Temperature
U4 = CMP-2000-07520-1: RF System on a Chip, 1.7 to 3.6 V, -40 to 85 degC, 73-Pin AQFN, RoHS, Tape and Reel; Manufacturer: Nordic Semiconductor
U6 = FDC6330L: IC LOAD SWITCH INT 20VIN SSOT-6; Manufacturer: Fairchild Semiconductor
U7 = BGA725L6: Silicon Germanium Low Noise Amplifier for Global Navigation Satellite Systems (GNSS), 1550 - 1615 MHz, 20 dB Gain, TSLP-6-2, Green; Manufacturer: Infineon; Gain (typ): 20 dB; F (typ): 0.65 dB; I (typ): 3.6 mA; Green: yes; P-1dB (in): -16
U8 = B9415: SAW filter; PartNumber: BGA725L6; Manufacturer: Infineon; Gain (typ): 20 dB; F (typ): 0.65 dB; I (typ): 3.6 mA; Frequency (f): 1550 - 1615 MHz; Green: yes; P-1dB (in): -16
U9 = bq5105xB
U10 = Module_RF_EXT_IO_4_2: Pour la conception du module RF
U11 = AS2953A
U12 = CMP-0859-00252-3: Single Inverter, DCK0005A, LARGE T&R; Manufacturer: Texas Instruments; Input Type: CMOS/TTL; Output Drive (IOL/IOH)(Max)(mA): 32/-32; Sub-Family: Inverting Buffer/Driver; VCC(Min)(V): 1.65; Bits(#): 1; Schmitt Trigger: No; Technology Family: LVC; Rating: Catalog; ICC @ Nom Voltage(Max)(mA): 0.01; tpd @ Nom Voltage(Max)(ns): 7.5,5.2,4.2,3.7; Voltage(Nom)(V): 1.8,2.5,3.3,5; F @ Nom Voltage(Max)(Mhz): 150; Output Type: CMOS; VCC(Max)(V): 5.5; Logic: Inverting
U13 = 2450AT43B100: ble ant 2.4 GHz
U15 U16 = DRV5021: Hall Effect Sensor
X1 = CMP-0449-00001-2: Crystal, 32 MHz, 8 pF, -10 to 70 degC, Surface Mount 2.5 x 2.0 mm; Manufacturer: Kyocera; Load Capacitance: 8 pF; Frequency Range: 32000 kHz; Packing: Tape and Reel; Motional Series Resistance: 50 ohm (max); Drive Level: 10uW (100uW max.)

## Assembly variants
production: not fitted J1 J_ANT_GPS J_ANT_RF J_LNA_IN J_LNA_OUT PAD_GND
